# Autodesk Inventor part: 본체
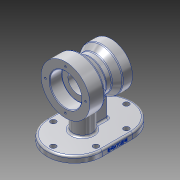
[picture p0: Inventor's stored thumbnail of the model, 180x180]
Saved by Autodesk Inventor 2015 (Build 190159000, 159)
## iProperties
Created: 2020-01
Part Number: 본체
Material: 알루미늄 6061
Document SubType Name: Modeling
Designer: LINEART-SSD.D4.16.05
Density: 2.7 g/cm^3
Appearance: 알루미늄 - 평지
Mass: 911.053 g
Surface Area: 638.133 cm^2
Volume: 337.427 cm^3
Author: LINEART-SSD.D4.16.05
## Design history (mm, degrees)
sketch "스케치1"
  geometry: L1 (-45, 25)-(-45, -25); L2 (45, -25)-(45, 25); L3 (0, 25)-(0, 0); L4 (0, 0)-(0, -25); A1 r 45 centre (0, 25) between (45, 25) and (-45, 25); A2 r 45 centre (0, -25) between (-45, -25) and (45, -25)
  constraints: 8 end point, 4 point on circle, 4 tangent, 2 centre point, 2 equal length, 2 vertical alignment, 1 collinear, 1 vertical
  dimensions: "d4" = 45 radius of A1; "d5" = 50 distance of L4.end L3.start
extrude "돌출1" new body sketch "스케치1" distance "d6" = 10; taper "d7" = 0 deg
sketch "스케치2"
  geometry: L1 (5, 3.199)-(5, 25); L2 (5, 25)-(-5, 25); L3 (-5, 25)-(-5, 3.199); A1 r 45 centre (0, -25) between (-45, -25) and (45, -25) reference; A2 r 16 centre (0, -12) between (-5, 3.199) and (5, 3.199); A3 r 45 centre (0, 25) between (45, 25) and (-45, 25) reference; 2 further points
  constraints: 6 end point, 2 point on circle, 2 vertical alignment, 1 centre point, 1 midpoint, 1 parallel
  dimensions: "d8" = 16 radius of A2; "d9" = 13 distance of A1.centre A2.centre; "d10" = 10 distance of L1.end L2.end; "d11" = 50 distance of A1.centre point (0, 25)
extrude "돌출2" join sketch "스케치2" distance "d12" = 70; taper "d13" = 0 deg
node "작업 평면2"
  node "작업 평면1"
sketch "스케치7"
  geometry: L1 (3.199, 80)-(-28, 80) reference; L2 (-70, 0)-(-70, 10) reference; L3 (-40, 80)-(-40, 120); L4 (-40, 120)-(-16, 120); L5 (-16, 120)-(-1.103, 107.5); L6 (-1.103, 107.5)-(8.289, 107.5); L7 (8.289, 107.5)-(19, 115); L8 (19, 115)-(35, 115); L9 (35, 115)-(35, 80); L10 (-40, 80)-(35, 80); L11 (-70, 80)-(67.993, 80); L12 (25, 10)-(25, 80) reference; 3 further points
  constraints: 18 end point, 2 horizontal, 2 horizontal alignment, 2 midpoint, 2 parallel, 2 perpendicular, 1 vertical
  dimensions: "d23" = 80 diameter of L4 L11; "d24" = 30 distance between parallel lines of L2 L3; "d25" = 55 diameter of L6 L11; "d26" = 24 distance of L3.end L4.end; "d27" = 16 distance of L7.end L8.end; "d28" = 70 diameter of L8 L11; "d29" = 10 distance between parallel lines of L12 L9; "d30" = 40 deg angle of L6 L5; "d31" = 35 deg angle of L7 L6
revolve "회전1" sketch "스케치7" stored, may be unused: angle "d32" = 90 deg
sketch "스케치8"
  geometry: C1 r 40 at (0, 0) reference; C2 r 26 at (0, 0); 1 further point
  constraints: 1 centre point, 1 coincident
  dimensions: "d33" = 52 diameter of C2
extrude "돌출5" cut sketch "스케치8" distance "d34" = 20; taper "d35" = 0 deg
sketch "스케치9"
  geometry: C1 r 35 at (0, 0) reference; C2 r 20 at (0, 0); 1 further point
  constraints: 1 centre point, 1 coincident
  dimensions: "d36" = 40 diameter of C2
extrude "돌출6" cut sketch "스케치9" distance "d37" = 17; taper "d38" = 0 deg
sketch "스케치10"
  geometry: C1 r 20 at (0, 0) reference; C2 r 16 at (0, 0); 1 further point
  constraints: 1 centre point, 1 coincident
  dimensions: "d39" = 32 diameter of C2
extrude "돌출7" cut sketch "스케치10" stored distance "d40" = 17; taper "d41" = 0 deg
sketch "스케치11" dims "d42" = 66
  geometry: C1 r 40 at (0, 0) reference; 6 further points
  constraints: 2 vertical alignment, 1 coincident, 7 other
  dimensions: "d45" = 360 deg dimension on C1.centre point (0, 33) (derived)
hole "구멍1" sketch "스케치11" at (0, 33), (-33, 0), (0, -33), (33, 0) diameter "d47" = 3.242; stored, may be unused: countersink angle "d51" = 90 deg, drill point angle "d53" = 118 deg; dims "d48" = 9, "d49" = 4, "d50" = 2, "d52" = 11
sketch "스케치12" dims "d54" = 55
  geometry: C1 r 35 at (0, 0) reference; 6 further points
  constraints: 2 vertical alignment, 1 coincident, 7 other
  dimensions: "d57" = 360 deg dimension on C1.centre point (0, -27.5) (derived)
hole "구멍2" sketch "스케치12" at (0, -27.5), (27.5, 0), (0, 27.5), (-27.5, 0) diameter "d59" = 3.242; stored, may be unused: countersink angle "d63" = 90 deg, drill point angle "d65" = 118 deg; dims "d60" = 9, "d61" = 4, "d62" = 2, "d64" = 11
sketch "스케치13"
  geometry: L1 (0, -25)-(0, 25); L2 (35, -25)-(35, 25); L3 (-35, 25)-(-35, -25); L4 (45, -25)-(45, 25) reference; A1 r 45 centre (0, 25) between (45, 25) and (-45, 25) reference; A2 r 45 centre (0, -25) between (-45, -25) and (45, -25) reference; A3 r 35 centre (0, -25) between (-35, -25) and (35, -25); A4 r 35 centre (0, 25) between (35, 25) and (-35, 25); 7 further points
  constraints: 8 end point, 6 point on circle, 4 coincident, 4 tangent, 2 centre point, 1 midpoint, 1 parallel, 1 vertical
  dimensions: "d66" = 10 distance between parallel lines of L4 L2
hole "구멍3" sketch "스케치13" at (0, 60), (0, -60), (-35, -25), (-35, 25), (35, 25), (35, -25) diameter "d67" = 9; stored, may be unused: countersink angle "d71" = 90 deg, drill point angle "d73" = 0 deg; dims "d68" = 9, "d69" = 4, "d70" = 2, "d72" = 11
fillet "모깎기1" dims "d74" = 0.3
chamfer "모따기1" distance "d75" = 1; stored, may be unused: second distance "d76" = 2, angle "d77" = 45 deg
chamfer "모따기2" distance "d78" = 1; stored, may be unused: second distance "d79" = 2, angle "d80" = 45 deg
fillet "모깎기2" dims "d81" = 3
sketch "스케치14"
  geometry: L1 (0, 0)-(0, 50) reference; L2 (0, -45)-(-7, -45) reference; 2 further points
  constraints: 1 other
  dimensions: "d82" = 4 distance from line of L1 point (-4, 25); "d83" = 70 distance from line of L2 point (-4, 25)
feature "엠보싱1" sketch "스케치14" dims "d4" = 45, "d5" = 50, "d84" = 0.5, "d85" = 0
node "솔리드1"
